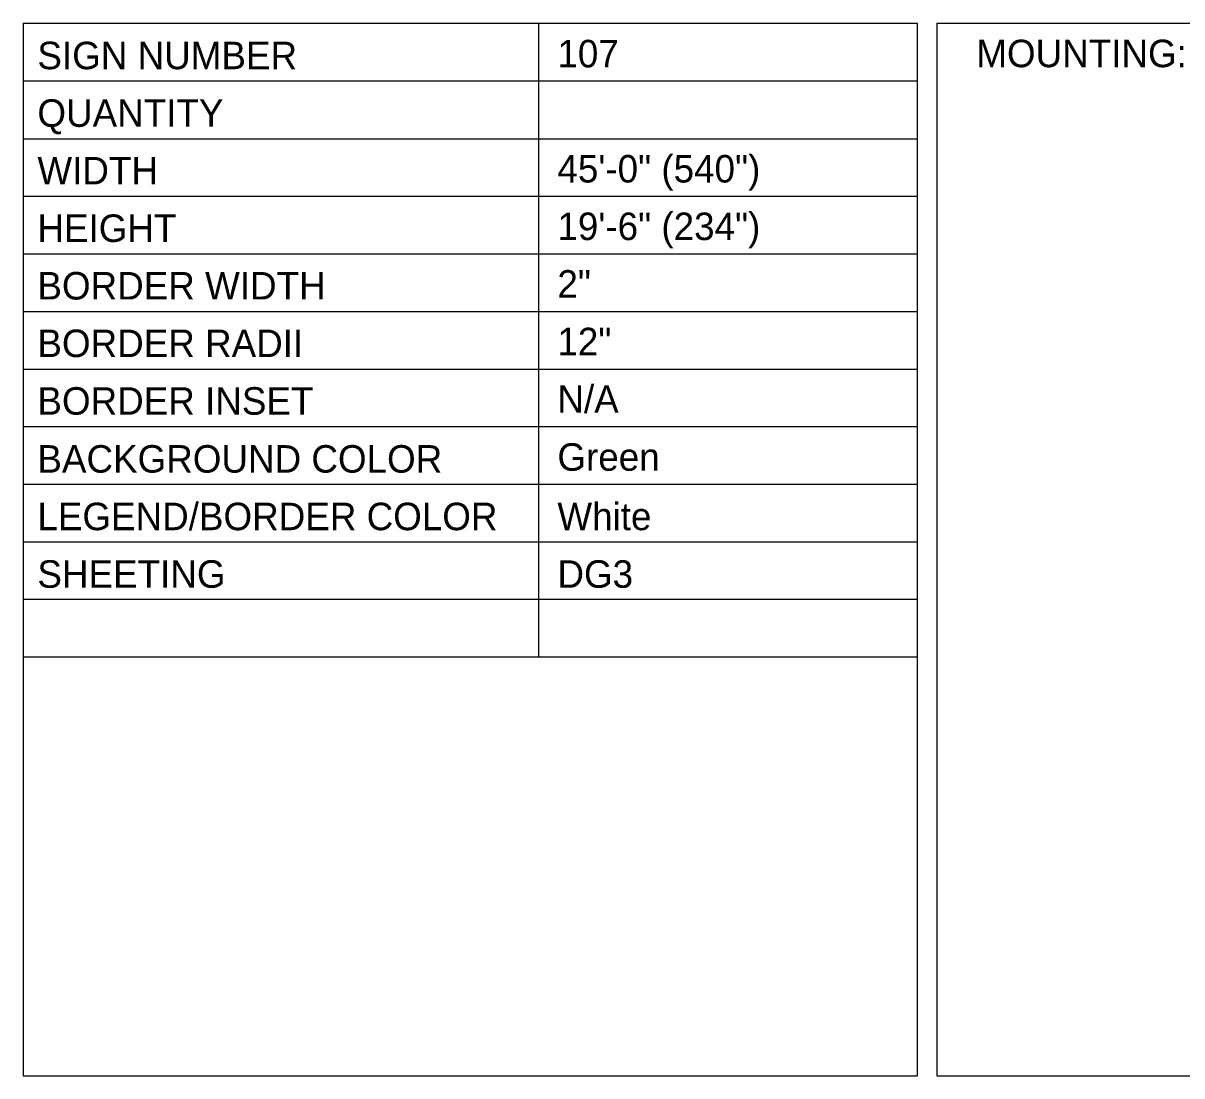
# Model space of a CAD drawing. Extents: x 531799 to 532094, y 1531149 to 1533620.
# Drawn here: x 531804.41 to 531829.46, y 1531174.3 to 1531197.08 of the extents above; entities that cross this region are included whole.
import ezdxf

# ---------------------------------------------------------------- set-up
doc = ezdxf.new("R2010")
doc.units = 0
for name, color, linetype in [('SumBoxLines_dp', 7, 'Continuous'), ('TextLabel', 7, 'Continuous'), ('TextMisc', 7, 'Continuous')]:
    doc.layers.add(name, color=color, linetype=linetype)

msp = doc.modelspace()

# ---------------------------------------------------------------- linework, layer by layer
at = {"layer": 'SumBoxLines_dp'}
for p, q in [((531804.413, 1531197.077), (531804.413, 1531174.302)), ((531804.413, 1531197.077), (531823.746, 1531197.077)), ((531815.556, 1531197.073), (531815.556, 1531183.366)), ((531823.746, 1531197.077), (531823.746, 1531174.302)), ((531824.171, 1531197.077), (531824.171, 1531174.302)), ((531824.171, 1531197.077), (531878.771, 1531197.077)), ((531804.413, 1531195.831), (531823.746, 1531195.831)), ((531804.413, 1531194.577), (531823.746, 1531194.577)), ((531804.413, 1531193.331), (531823.746, 1531193.331)), ((531804.413, 1531192.086), (531823.746, 1531192.086)), ((531804.413, 1531190.84), (531823.746, 1531190.84)), ((531804.413, 1531189.594), (531823.746, 1531189.594)), ((531804.413, 1531188.349), (531823.746, 1531188.349)), ((531804.413, 1531187.103), (531823.746, 1531187.103)), ((531804.413, 1531185.858), (531823.746, 1531185.858)), ((531804.413, 1531184.612), (531823.746, 1531184.612)), ((531804.413, 1531183.366), (531823.746, 1531183.366)), ((531804.413, 1531174.302), (531823.746, 1531174.302)), ((531824.171, 1531174.302), (531878.771, 1531174.302))]:
    msp.add_line(p, q, dxfattribs=at)

# ---------------------------------------------------------------- texts
at = {"layer": 'TextLabel'}
for s, p in [('107', (531815.964, 1531196.12)), ('MOUNTING: OVERHEAD TRUSS (OT-X)', (531825.021, 1531196.124)), ('45\'-0" (540")', (531815.964, 1531193.629)), ('19\'-6" (234")', (531815.964, 1531192.384)), ('2"', (531815.964, 1531191.138)), ('12"', (531815.964, 1531189.892)), ('N/A', (531815.964, 1531188.647)), ('Green', (531815.964, 1531187.393)), ('White', (531815.964, 1531186.107)), ('DG3', (531815.964, 1531184.861))]:
    msp.add_text(s, height=0.595, dxfattribs=at).set_placement(p)
at = {"layer": 'TextMisc'}
for s, p in [('SIGN NUMBER', (531804.721, 1531196.08)), ('QUANTITY', (531804.721, 1531194.834)), ('WIDTH', (531804.721, 1531193.589)), ('HEIGHT', (531804.721, 1531192.343)), ('BORDER WIDTH', (531804.721, 1531191.098)), ('BORDER RADII', (531804.721, 1531189.852)), ('BORDER INSET', (531804.721, 1531188.606)), ('BACKGROUND COLOR', (531804.721, 1531187.352)), ('LEGEND/BORDER COLOR', (531804.721, 1531186.107)), ('SHEETING', (531804.721, 1531184.861))]:
    msp.add_text(s, height=0.595, dxfattribs=at).set_placement(p)

doc.saveas('drawing.dxf')
